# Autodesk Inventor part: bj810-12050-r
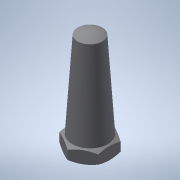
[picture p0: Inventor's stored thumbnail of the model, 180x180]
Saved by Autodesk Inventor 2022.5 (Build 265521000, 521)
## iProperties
Created: 2016-12
Part Number: bj810-12050-r
Material: 一般
Document SubType Name: Modeling
Designer: imaocorp
Density: 1 g/cm^3
Appearance: 既定
Author: imaocorp
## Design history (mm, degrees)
node "bj810-12050-r.x_t1"
node "bj810-12050-r"
node "Base1"
